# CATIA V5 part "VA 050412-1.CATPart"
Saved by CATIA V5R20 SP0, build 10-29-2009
Part number: VA 050412-1
Revision: ANY
Definition: UNKNOWN
Nomenclature: VA 050412-1
Source: Unknown
Bounding box of the stored display mesh (mm): x -1.501 to 1.501, y 0 to 10.3, z -1.501 to 1.501
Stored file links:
  C:\Users\Utente\Desktop\IO LAVORO\3D X SITO CF\CUMSA\3D files VA\VA 050412\VA 050412-1.CATPart
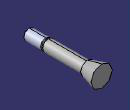
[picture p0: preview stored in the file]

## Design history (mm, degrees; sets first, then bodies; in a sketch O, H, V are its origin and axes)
Body1 "Revolución1" (main body)
  Solid1: solid without history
